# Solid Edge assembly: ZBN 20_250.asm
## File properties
Title: Zylinder
Author: bmolnar
Template: iso metric assembly.asm
Last saved by: bmolnar
Revision: 25
Application: Solid Edge
Username: bmolnar
Dokumentum tartalom típus: 1
Document Number: ZBN 20/250
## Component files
Kit_1.par
Kit_2.par
Profilrohr.par
Kolbenstange.par
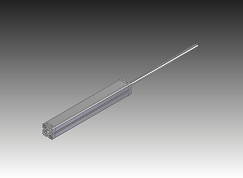
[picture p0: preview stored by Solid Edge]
